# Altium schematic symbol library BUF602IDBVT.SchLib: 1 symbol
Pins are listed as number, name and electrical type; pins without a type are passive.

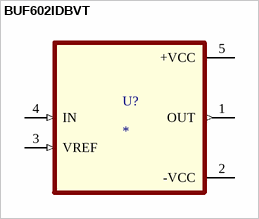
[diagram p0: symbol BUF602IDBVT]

## BUF602IDBVT
designator U?
1000MHz,Wide Bandwidth, High-Speed, Closed Loop Buffer 5-SOT-23 -45 to 85; MF: Texas Instruments; MP: BUF602IDBVT
footprint BUF602IDBVT
pins: 1 OUT (out), 2 -VCC (power), 3 VREF (in), 4 IN (in), 5 +VCC (power)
